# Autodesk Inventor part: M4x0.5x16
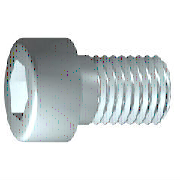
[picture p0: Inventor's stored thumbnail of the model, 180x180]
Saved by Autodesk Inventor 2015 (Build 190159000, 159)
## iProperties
Created: 2014-07
Part Number: M4x0.5x16
Material: 강, 연강
Description: 6각머리 태핑 나사
Document SubType Name: Modeling
Standard: KS B 1003
Designer: KYOUNG IL JANG
Standards Organization: KS
Language: ko-KR
Size Designation: M 4 x 16
Categories: <MemberInstance><Categories><Category DisplayName="조임쇠" InternalName="e4da775c-781d-43d5-af7c-5136215cf5a6" Mnemonic="FSTN"><Category DisplayName="볼트" InternalN
Density: 1 g/cm^3
Appearance: 강철
Company: 한국ATC센터
IsCustomPart: 1
Author: KYOUNG IL JANG
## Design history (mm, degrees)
sketch "스케치1"
  geometry: L1 (-1, 0)-(16, 0); L2 (16, 0)-(16, 2); L3 (16, 2)-(1.75, 2); L4 (1.75, 2)-(1.32, 2); L5 (1.32, 2)-(0, 2); L6 (0, 2)-(0, 3.5); L7 (0, 3.5)-(-4, 3.5); L8 (-4, 3.5)-(-4, 1.732); L9 (-4, 1.732)-(-2, 1.732); L10 (-2, 1.732)-(-1, 0); L11 (-8, 0)-(20, 0) reference; L12 (0, -0.7)-(0, 4.2) reference; L13 (1.75, 2)-(0, 2)
  constraints: 22 end point, 6 parallel, 2 collinear, 2 perpendicular, 1 horizontal, 1 point on line
  dimensions: "d1" = 14.25 distance from line of L3.end L2 (= GEL); "d2" = 0.42952 distance of L4.end L3.end (computed from GAL); "d3" = 4 distance between parallel lines of L8 L6 (= KOH); "d4" = 2 distance of L8.end L9.end (= INTI); "d5" = 60 deg angle of L10 L1; "d6" = 4 diameter of L3 L1 (= GD); "d7" = 4 diameter of L5 L1 (= BDM); "d8" = 3.4641 diameter of L9 L1 (= 1.1547 x SW); "d9" = 7 diameter of L7 L1 (= KOD); "d26" = 16 distance between parallel lines of L12 L2 (= NLG)
revolve "본체" sketch "스케치1" stored, may be unused: angle "d10" = 90 deg
sketch "스케치2"
  geometry: L1 (0, -4.9)-(0, 4.9) reference; L2 (-4.9, 0)-(4.9, 0) reference; L3 (1.732, 0)-(0.866, -1.5); L4 (0.866, -1.5)-(-0.866, -1.5); L5 (-0.866, -1.5)-(-1.732, 0); L6 (-1.732, 0)-(-0.866, 1.5); L7 (-0.866, 1.5)-(0.866, 1.5); L8 (0.866, 1.5)-(1.732, 0); 2 further points
  constraints: 12 end point, 1 coincident, 1 horizontal alignment, 1 point on line, 12 other
extrude "슬롯" join sketch "스케치2" stored distance "d11" = 10; taper "d12" = 0 deg
workplane "Work Plane1"
fillet "Fillet2" dims "d30" = 0.1 (= R)
body "Solid1"
fillet "모깎기1" dims "d17" = 0.4 (= RR)
feature "스레드" dims "d13" = 14.25 (= GEL), "d14" = 0
chamfer "모따기1" distance "d15" = 0.42941 (= -0.5 x SPD + 0.5 x GD); stored, may be unused: second distance "d16" = 0.42941 (= GUL), angle "d27" = 45 deg
other parameters: "GD" = 4 (= NND) [user parameter; used in 2 equation terms], "NLG" = 16 [user parameter; used in 1 equation term], "GEL" = 14.25 [user parameter; used in 2 equation terms], "KOD" = 7 [user parameter; used in 1 equation term], "KOH" = 4 [user parameter; used in 1 equation term], "INTI" = 2 [user parameter; used in 1 equation term], "GAL" = 0.42941 (= 0.61345 x PTC) [user parameter; used in 1 equation term], "GUL" = 0.42941 (= 0.61345 x PTC) [user parameter; used in 1 equation term], "BDM" = 4 (= NND) [user parameter; used in 1 equation term], "SW" = 3 [user parameter; used in 2 equation terms], "RR" = 0.4 [user parameter; used in 1 equation term], "SPD" = 3.14117 (= NND - 1.2269 x PTC) [user parameter; used in 1 equation term], "d19" = 0, "d28" = 0, "d29" = 0, "R" = 0.1 [user parameter; used in 1 equation term], "PHH" = 0.2 [user parameter], "GD1" = 3.14117 (= THREADDIA - 1.2269 x PTC) [user parameter], "THREADDIA" = 4 [user parameter; used in 1 equation term], "FAWI" = 45 deg [user parameter], "TPU" = 14.28571 (computed from PTC) [user parameter], "PTC" = 0.7 [user parameter; used in 5 equation terms], "NND" = 4 [user parameter; used in 3 equation terms], "TOA" = 30 deg [user parameter], "E0" = 3.465 (= 1.155 x SW) [user parameter]
